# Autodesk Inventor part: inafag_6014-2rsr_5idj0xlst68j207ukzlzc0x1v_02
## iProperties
Shininess: 64.0
Angle Display Precision: 2
Document Length Units: 11269
Document Angle Units: 11279
Document Time Units: 11290
Document Mass Units: 11283
Document Length Units Precision: 3
Document Angle Units Precision: 2
Compacted: True
Created: 2008-08
Part Number: inafag_6014-2rsr_5idj0xlst68j207ukzlzc0x1v_02
Document SubType Name: Modeling
Designer: tpomodeler
Density: 0.0
Volumn: 0.0
Area: 0.0
PropertySet Name: Model Information
Control State: 0
Master: False
Checked Out: False
Author: tpomodeler
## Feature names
1. inafag_6014-2rsr_5idj0xlst68j207ukzlzc0x1v
